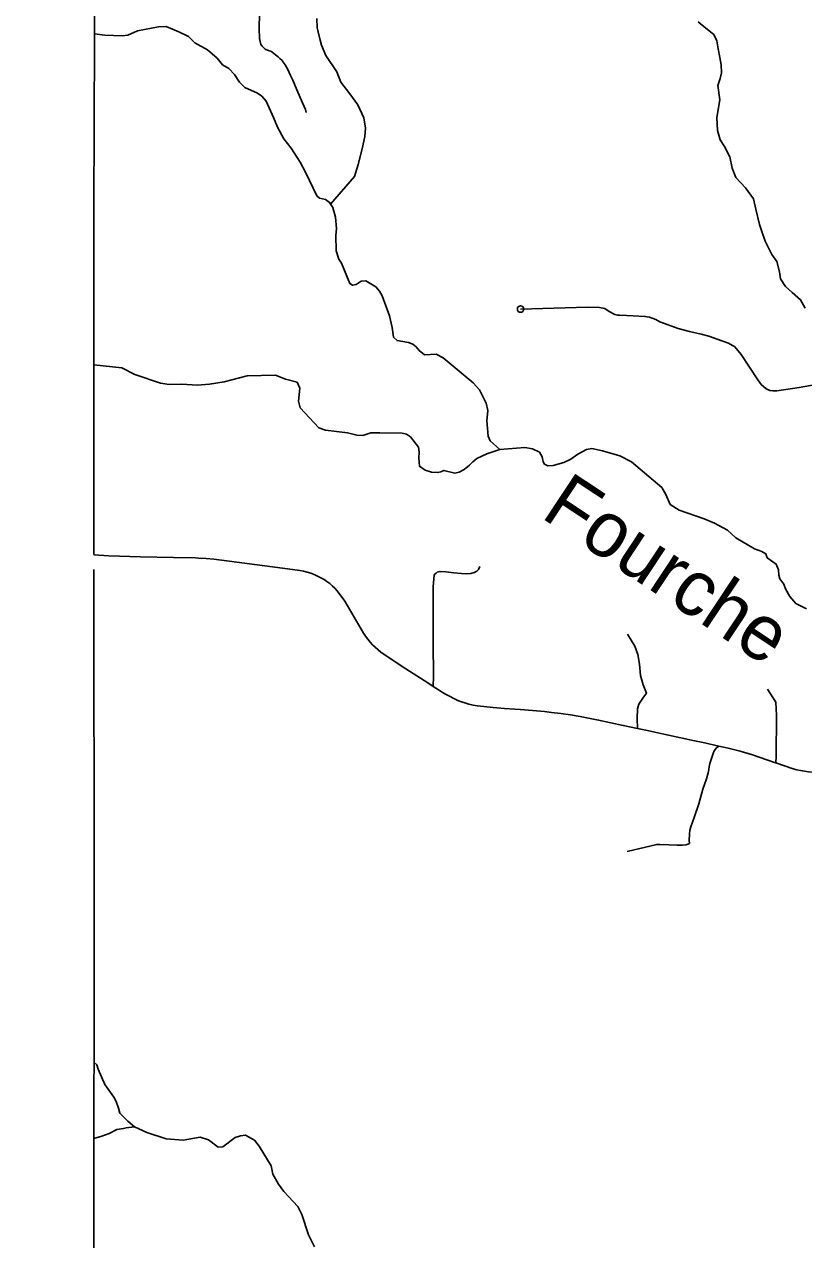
# Model space of a CAD drawing. Extents: x -19 to 366, y -4 to 359.
# Drawn here: x 139.293 to 140.416, y 188.535 to 190.286 of the extents above; entities that cross this region are included whole.
import ezdxf

# ---------------------------------------------------------------- set-up
doc = ezdxf.new("R2010")
doc.units = 0
for name, color, linetype in [('R_Alt Surface', 7, 'Continuous'), ('R_ROW', 7, 'Continuous'), ('R_ROW Annot', 7, 'Continuous'), ('R_Temp Easement', 7, 'Continuous'), ('Sheet Fence', 7, 'Continuous')]:
    doc.layers.add(name, color=color, linetype=linetype)

msp = doc.modelspace()

# ---------------------------------------------------------------- linework, layer by layer
at = {"layer": 'R_Alt Surface'}
msp.add_lwpolyline([(139.3808, 187.0227), (139.3884, 188.0149), (139.3927, 188.5383), (139.3933, 189.009), (139.3933, 189.0178), (139.3929, 189.5007)], dxfattribs=at)
at = {"layer": 'R_ROW'}
for points in [[(139.3949, 190.5096), (139.3927, 190.0208), (139.3929, 189.5225)], [(139.6986, 190.1593), (139.6977, 190.1636), (139.6961, 190.1679), (139.6937, 190.1732), (139.6853, 190.1919), (139.6794, 190.2058), (139.6763, 190.2126), (139.6723, 190.2211), (139.6688, 190.228), (139.6659, 190.232), (139.6641, 190.2343), (139.6611, 190.237), (139.6585, 190.2395), (139.6545, 190.2423), (139.65, 190.2464), (139.6481, 190.2477), (139.6455, 190.2483), (139.6399, 190.2507), (139.6353, 190.2549), (139.6335, 190.2574), (139.6316, 190.2659), (139.6313, 190.2802), (139.6315, 190.3021)], [(140.4387, 189.7685), (140.4093, 189.7632), (140.3769, 189.7583), (140.3712, 189.7581), (140.3668, 189.7586), (140.3615, 189.7612), (140.3543, 189.7674), (140.3496, 189.7741), (140.3253, 189.8104), (140.3189, 189.8189), (140.3159, 189.8221), (140.3131, 189.8237), (140.3074, 189.827), (140.2977, 189.8303), (140.2791, 189.8368), (140.2681, 189.8397), (140.2511, 189.8439), (140.2348, 189.8483), (140.2085, 189.8579), (140.2025, 189.8612), (140.1936, 189.8644), (140.1869, 189.8656), (140.1699, 189.8661), (140.1508, 189.8673), (140.1472, 189.8675), (140.1434, 189.8684), (140.1354, 189.8725), (140.1292, 189.8768), (140.1215, 189.8783), (140.1043, 189.8789), (140.0078, 189.8761)], [(139.882, 189.3324), (139.8743, 189.3373), (139.8373, 189.3609), (139.8065, 189.3815), (139.7945, 189.392), (139.7908, 189.396), (139.7875, 189.4002), (139.7844, 189.4046), (139.7815, 189.4092), (139.7714, 189.4264), (139.7544, 189.4552), (139.7434, 189.47), (139.74, 189.4737), (139.7365, 189.4771), (139.7328, 189.4804), (139.7288, 189.4834), (139.7247, 189.4862), (139.72, 189.489), (139.7152, 189.4914), (139.7104, 189.4936), (139.7054, 189.4954), (139.7003, 189.497), (139.6952, 189.4983), (139.6899, 189.4993), (139.6503, 189.5048), (139.5768, 189.5142), (139.5657, 189.5155), (139.5546, 189.5165), (139.5435, 189.5172), (139.5392, 189.5174), (139.5077, 189.5183), (139.4602, 189.5192), (139.4143, 189.5205), (139.3929, 189.5217)], [(139.9491, 189.505), (139.947, 189.5008), (139.9447, 189.4983), (139.9408, 189.4963), (139.9361, 189.495), (139.9299, 189.4943), (139.9227, 189.4948), (139.9118, 189.4958), (139.9, 189.4975), (139.8918, 189.498), (139.8897, 189.4976), (139.8877, 189.4969), (139.8859, 189.4957), (139.8843, 189.4942), (139.8831, 189.4924), (139.8819, 189.4762), (139.8816, 189.4444), (139.882, 189.3991), (139.8822, 189.3427), (139.8818, 189.3367), (139.882, 189.3324)], [(140.1763, 189.2717), (140.1556, 189.2762), (140.1202, 189.2837), (140.0934, 189.289), (140.0797, 189.2913), (140.0659, 189.2933), (140.0521, 189.2949), (140.042, 189.296), (140.0076, 189.2989), (139.9996, 189.2994), (139.9845, 189.3004), (139.9681, 189.3017), (139.9455, 189.3041), (139.9394, 189.3053), (139.9333, 189.3068), (139.9273, 189.3085), (139.9213, 189.3106), (139.9185, 189.3116), (139.8985, 189.3218), (139.882, 189.3324)], [(140.2935, 189.2463), (140.2871, 189.2477), (140.2709, 189.2513), (140.2582, 189.254), (140.2387, 189.2582), (140.2141, 189.2635), (140.1882, 189.2691), (140.1763, 189.2717)], [(140.3753, 189.222), (140.3733, 189.2227), (140.342, 189.2335), (140.3241, 189.2389), (140.3069, 189.2433), (140.2935, 189.2463)], [(140.6113, 189.1984), (140.6087, 189.1993), (140.6005, 189.2017), (140.5923, 189.2039), (140.5839, 189.2058), (140.5755, 189.2074), (140.5671, 189.2086), (140.5586, 189.2096), (140.5477, 189.2104), (140.5372, 189.2109), (140.5267, 189.211), (140.5162, 189.2109), (140.5118, 189.2107), (140.4694, 189.2094), (140.4367, 189.2087), (140.4223, 189.2094), (140.4167, 189.21), (140.4112, 189.2109), (140.4058, 189.2121), (140.4004, 189.2136), (140.3753, 189.222)]]:
    msp.add_lwpolyline(points, dxfattribs=at)
msp.add_circle((140.0078, 189.8761), 0.00473, dxfattribs=at)
at = {"layer": 'R_ROW Annot'}
for points in [[(140.1763, 189.2717), (140.1755, 189.2863), (140.1764, 189.2998), (140.1783, 189.3066), (140.1837, 189.3155), (140.1889, 189.3224), (140.1842, 189.3344), (140.1807, 189.3482), (140.1789, 189.3646), (140.1768, 189.3781), (140.1724, 189.3904), (140.1619, 189.4075)], [(140.3753, 189.222), (140.3757, 189.2319), (140.3763, 189.2906), (140.3754, 189.3095), (140.3633, 189.3283)], [(140.2935, 189.2463), (140.2898, 189.2436), (140.2885, 189.242), (140.2864, 189.2393), (140.285, 189.2355), (140.2806, 189.2213), (140.2792, 189.2166), (140.2791, 189.2126), (140.2779, 189.2078), (140.2757, 189.1993), (140.2705, 189.1844), (140.2643, 189.1632), (140.2578, 189.1436), (140.253, 189.1301), (140.2516, 189.125), (140.2513, 189.1195), (140.2505, 189.1102), (140.2511, 189.1059)], [(140.2511, 189.1059), (140.2465, 189.1042), (140.2411, 189.1033), (140.2333, 189.1035), (140.2212, 189.1038), (140.2082, 189.1045), (140.204, 189.1046), (140.1611, 189.0944)]]:
    msp.add_lwpolyline(points, dxfattribs=at)
at = {"layer": 'R_Temp Easement'}
for points in [[(139.7341, 190.0273), (139.7684, 190.0671), (139.7738, 190.0845), (139.7796, 190.1068), (139.7833, 190.1249), (139.7842, 190.1369), (139.7817, 190.1518), (139.7734, 190.1706), (139.7619, 190.1861), (139.7488, 190.2032), (139.743, 190.2181), (139.7272, 190.2414), (139.7211, 190.2566), (139.7189, 190.2636), (139.7156, 190.2776), (139.7145, 190.2815), (139.7142, 190.2946)], [(139.9778, 189.6735), (139.9638, 189.6861), (139.9612, 189.6929), (139.9589, 189.7149), (139.9604, 189.7297), (139.9582, 189.7407), (139.9487, 189.7597), (139.9396, 189.7696), (139.8962, 189.806), (139.886, 189.811), (139.8693, 189.8102), (139.8618, 189.8163), (139.8572, 189.8216), (139.8523, 189.8254), (139.8463, 189.8281), (139.8297, 189.8307), (139.8247, 189.8357), (139.8229, 189.8493), (139.8187, 189.8664), (139.8085, 189.8953), (139.8047, 189.9021), (139.7994, 189.9082), (139.7847, 189.9169), (139.7779, 189.9162), (139.7711, 189.9116), (139.7658, 189.9105), (139.7616, 189.9131), (139.7495, 189.9424), (139.7461, 189.948), (139.742, 189.9602), (139.7416, 189.9822), (139.7424, 189.9921), (139.7412, 190.0084), (139.7374, 190.0225), (139.7325, 190.0297), (139.7269, 190.0342), (139.7182, 190.0361), (139.714, 190.0392), (139.6985, 190.0722), (139.6902, 190.0878), (139.677, 190.1079), (139.6668, 190.1212), (139.6573, 190.1383), (139.652, 190.1519), (139.6411, 190.1755), (139.635, 190.1827), (139.6286, 190.1872), (139.6105, 190.1956), (139.6029, 190.2032), (139.5954, 190.2142), (139.5874, 190.2225), (139.5783, 190.2282), (139.5704, 190.2377), (139.5568, 190.2495), (139.5383, 190.2598), (139.5292, 190.2689), (139.5156, 190.2757), (139.4971, 190.2833), (139.4861, 190.2829), (139.4559, 190.2772), (139.4419, 190.2708), (139.4336, 190.2696), (139.4087, 190.2708), (139.3938, 190.2725)], [(140.2638, 190.2902), (140.2747, 190.2808), (140.2861, 190.2718), (140.2906, 190.2624), (140.2924, 190.2512), (140.2946, 190.2388), (140.2969, 190.2278), (140.297, 190.2166), (140.2953, 190.2084), (140.2921, 190.1981), (140.2949, 190.1777), (140.2905, 190.152), (140.2914, 190.1333), (140.2954, 190.1199), (140.3013, 190.1105), (140.3092, 190.0953), (140.3126, 190.0793), (140.3177, 190.0656), (140.3318, 190.0507), (140.3433, 190.0347), (140.3465, 190.0201), (140.3521, 189.9981), (140.3547, 189.9892), (140.3602, 189.9738), (140.3697, 189.9545), (140.3767, 189.9444), (140.3807, 189.9297), (140.3824, 189.9195), (140.3896, 189.9085), (140.3991, 189.9001), (140.4109, 189.8894), (140.4179, 189.8774)], [(139.3928, 189.7957), (139.4332, 189.7913), (139.4521, 189.7818), (139.4888, 189.7693), (139.5016, 189.7674), (139.5194, 189.7678), (139.5424, 189.7666), (139.5598, 189.7678), (139.5806, 189.7712), (139.6139, 189.7799), (139.6547, 189.7806), (139.669, 189.775), (139.6857, 189.7708), (139.6898, 189.762), (139.6879, 189.7434), (139.6902, 189.7336), (139.717, 189.7047), (139.7265, 189.7017), (139.7582, 189.6979), (139.7718, 189.6945), (139.7805, 189.6941), (139.7919, 189.6979), (139.8051, 189.6979), (139.8372, 189.6971), (139.8436, 189.6956), (139.8493, 189.6918), (139.8606, 189.677), (139.8618, 189.6698), (139.861, 189.661), (139.8622, 189.6496), (139.8705, 189.6439), (139.8792, 189.6409), (139.8886, 189.6405), (139.8928, 189.6413), (139.8973, 189.6436), (139.9132, 189.6398), (139.9192, 189.6409), (139.9264, 189.6447), (139.9343, 189.6511), (139.9389, 189.6561), (139.9449, 189.6606), (139.9589, 189.6675), (139.9778, 189.6735)], [(139.9778, 189.6735), (140.0137, 189.6766), (140.0247, 189.6747), (140.0349, 189.6701), (140.039, 189.6633), (140.0402, 189.6557), (140.0424, 189.6527), (140.047, 189.6504), (140.0545, 189.6508), (140.07, 189.6549), (140.0802, 189.6599), (140.09, 189.6671), (140.1029, 189.6735), (140.1105, 189.675), (140.1256, 189.672), (140.1505, 189.6644), (140.1675, 189.656), (140.211, 189.6188), (140.217, 189.609), (140.2231, 189.5945), (140.2363, 189.5862), (140.2722, 189.574), (140.2873, 189.5676), (140.3058, 189.5577), (140.3179, 189.5463), (140.3448, 189.5307), (140.3553, 189.5269), (140.361, 189.5235), (140.3629, 189.5178), (140.3761, 189.5087), (140.3792, 189.5004), (140.3799, 189.4924), (140.3814, 189.4871), (140.3871, 189.4795), (140.3894, 189.4727), (140.3954, 189.462), (140.4045, 189.4518), (140.4196, 189.4442)], [(139.393, 188.7908), (139.3973, 188.7872), (139.3992, 188.7808), (139.409, 188.7587), (139.4219, 188.7405), (139.4253, 188.7341), (139.4287, 188.7246), (139.4302, 188.7174), (139.4419, 188.7056), (139.4513, 188.6976), (139.4691, 188.6893), (139.4971, 188.6805), (139.5216, 188.6782), (139.5462, 188.6828), (139.5579, 188.679), (139.5719, 188.6684), (139.5787, 188.6687), (139.5965, 188.6824), (139.6044, 188.6847), (139.6112, 188.6854), (139.6244, 188.6782), (139.6309, 188.6699), (139.6482, 188.6414)], [(139.3929, 188.681), (139.4046, 188.6842), (139.4152, 188.6882), (139.4263, 188.6938), (139.4356, 188.6954), (139.4397, 188.6963), (139.4513, 188.6976)], [(139.6482, 188.6414), (139.6509, 188.6296), (139.6588, 188.6148), (139.6668, 188.6046), (139.6868, 188.5829), (139.6925, 188.5712), (139.7023, 188.5419), (139.7106, 188.5245)]]:
    msp.add_lwpolyline(points, dxfattribs=at)
at = {"layer": 'Sheet Fence'}
for points in [[(146.7783, 1.697), (146.5788, 10.3131), (146.3785, 18.9294), (146.1776, 27.5458), (145.9759, 36.1624), (145.7736, 44.7791), (145.5705, 53.396), (145.3668, 62.013), (145.1624, 70.6301), (144.9572, 79.2474), (144.7514, 87.8648), (144.5449, 96.4823), (144.3377, 105.1), (144.1299, 113.7179), (143.9213, 122.3359), (143.712, 130.954), (143.5021, 139.5723), (143.2915, 148.1907), (143.0802, 156.8092), (142.8682, 165.4279), (142.6555, 174.0468), (142.4422, 182.6658), (142.2282, 191.2849), (142.0135, 199.9042), (141.7981, 208.5236), (141.582, 217.1432), (141.3653, 225.7629), (141.1479, 234.3828), (140.9298, 243.0028), (140.711, 251.623), (140.4916, 260.2433), (140.2715, 268.8638), (140.0508, 277.4844), (139.8293, 286.1051), (139.6072, 294.726), (139.3845, 303.3471), (139.161, 311.9683), (138.937, 320.5896), (138.7122, 329.2111), (138.4868, 337.8328), (138.2607, 346.4546)], [(139.4406, 1.5315), (139.2511, 10.1473), (139.0608, 18.7633), (138.8699, 27.3793), (138.6784, 35.9956), (138.4861, 44.6119), (138.2932, 53.2285), (138.0997, 61.8451), (137.9055, 70.4619), (137.7106, 79.0789), (137.5151, 87.6959), (137.319, 96.3132), (137.1221, 104.9306), (136.9247, 113.5481), (136.7265, 122.1658), (136.5278, 130.7836), (136.3283, 139.4016), (136.1282, 148.0197), (135.9275, 156.6379), (135.7261, 165.2564), (135.5241, 173.8749), (135.3214, 182.4936), (135.1181, 191.1125), (134.9141, 199.7315), (134.7095, 208.3506), (134.5043, 216.9699), (134.2984, 225.5894), (134.0919, 234.209), (133.8847, 242.8288), (133.6769, 251.4487), (133.4685, 260.0687), (133.2594, 268.6889), (133.0497, 277.3093), (132.8393, 285.9298), (132.6283, 294.5504), (132.4167, 303.1713), (132.2044, 311.7922), (131.9916, 320.4133), (131.778, 329.0346), (131.5639, 337.656), (131.3491, 346.2776)], [(0, 189.5162), (7.1121, 189.5206), (14.2243, 189.5339), (21.3364, 189.556), (28.4484, 189.5869), (35.5605, 189.6267), (42.6725, 189.6754), (49.7844, 189.7329), (56.8962, 189.7992), (64.0079, 189.8744), (71.1196, 189.9584), (78.2311, 190.0512), (85.3425, 190.1529), (92.4538, 190.2635), (99.5649, 190.3829), (106.6759, 190.5111), (113.7867, 190.6482), (120.8974, 190.7941), (128.0078, 190.9489), (135.1181, 191.1125), (142.2282, 191.2849), (149.338, 191.4662), (156.4476, 191.6563), (163.5569, 191.8553), (170.666, 192.0631), (177.7749, 192.2798), (184.8835, 192.5053), (191.9917, 192.7396), (199.0997, 192.9828), (206.2074, 193.2348), (213.3147, 193.4956), (220.4218, 193.7653), (227.5285, 194.0438), (234.6348, 194.3312), (241.7408, 194.6274), (248.8464, 194.9324), (255.9516, 195.2463), (263.0564, 195.569), (270.1608, 195.9005), (277.2648, 196.2409), (284.3683, 196.5901), (291.4715, 196.9481), (298.5741, 197.315), (305.6763, 197.6907), (312.7781, 198.0753), (319.8793, 198.4686), (326.9801, 198.8708), (334.0804, 199.2818), (341.1801, 199.7017)], [(0, 180.8999), (7.1228, 180.9044), (14.2457, 180.9176), (21.3685, 180.9397), (28.4912, 180.9706), (35.614, 181.0103), (42.7366, 181.0589), (49.8592, 181.1163), (56.9818, 181.1825), (64.1042, 181.2575), (71.2266, 181.3414), (78.3488, 181.4341), (85.4709, 181.5357), (92.5929, 181.646), (99.7147, 181.7652), (106.8364, 181.8933), (113.9579, 182.0301), (121.0793, 182.1758), (128.2005, 182.3303), (135.3214, 182.4936), (142.4422, 182.6658), (149.5627, 182.8468), (156.683, 183.0366), (163.8031, 183.2352), (170.9229, 183.4427), (178.0425, 183.659), (185.1617, 183.8841), (192.2807, 184.1181), (199.3994, 184.3608), (206.5178, 184.6124), (213.6359, 184.8728), (220.7537, 185.1421), (227.8711, 185.4201), (234.9881, 185.707), (242.1048, 186.0027), (249.2212, 186.3073), (256.3371, 186.6206), (263.4526, 186.9428), (270.5678, 187.2738), (277.6825, 187.6136), (284.7968, 187.9622), (291.9107, 188.3197), (299.0241, 188.6859), (306.1371, 189.061), (313.2495, 189.4449), (320.3615, 189.8377), (327.4731, 190.2392), (334.5841, 190.6495), (341.6946, 191.0687)]]:
    msp.add_spline(points, degree=3, dxfattribs=at)

# ---------------------------------------------------------------- texts
at = {"layer": 'R_Temp Easement'}
msp.add_text('Fourche', height=0.08, rotation=326.4781, dxfattribs=at).set_placement((140.035, 189.5768))

doc.saveas('drawing.dxf')
